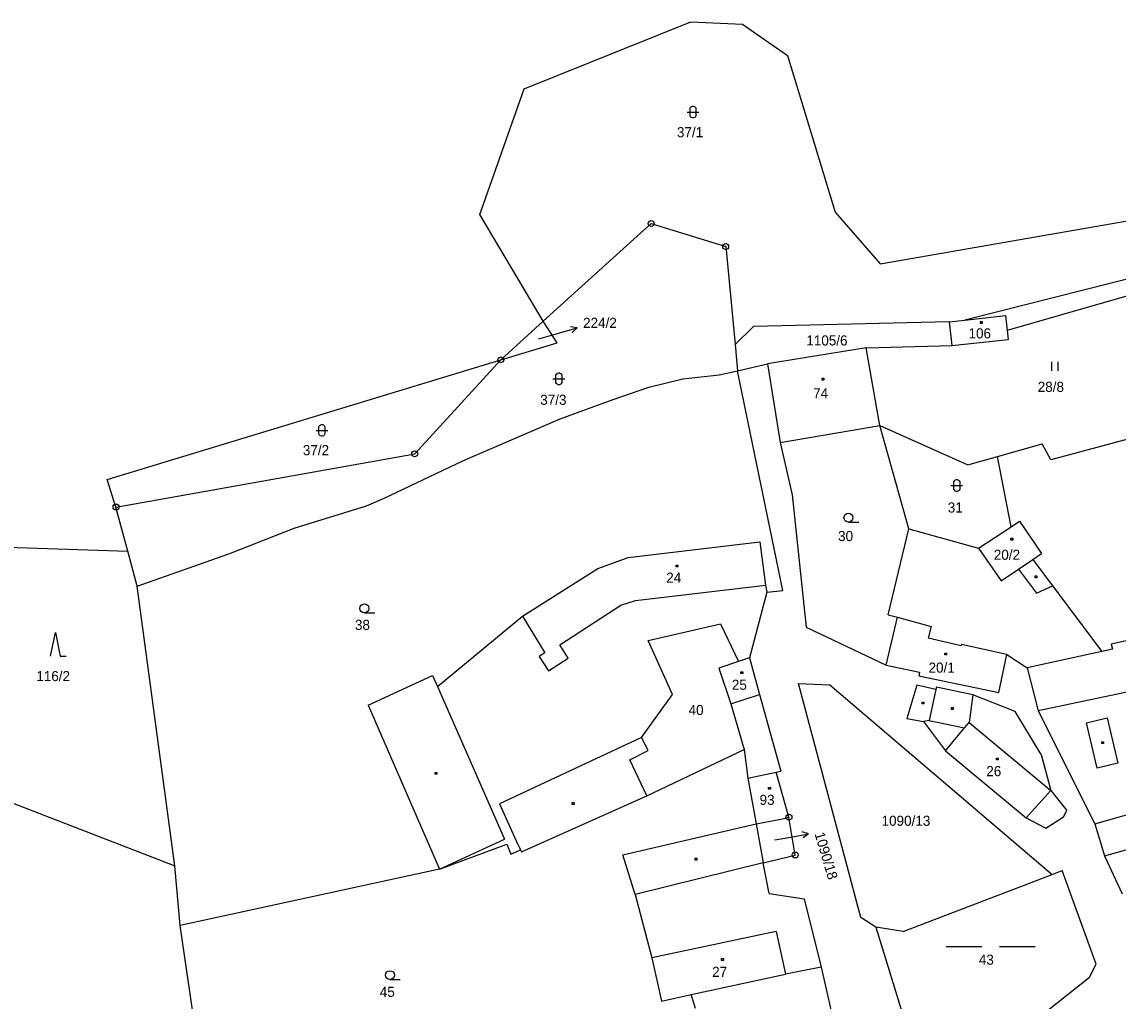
# Model space of a CAD drawing. Extents: x -794142 to -791199, y -1109267 to -1105626.
# Drawn here: x -793649.2 to -793464.4, y -1107661.7 to -1107496.8 of the extents above; entities that cross this region are included whole.
import ezdxf

# ---------------------------------------------------------------- set-up
doc = ezdxf.new("R2010")
doc.units = 0
for name, color, linetype in [('Komunikace', 7, 'Continuous'), ('Vrstva 1', 7, 'Continuous'), ('Vrstva 14', 7, 'Continuous'), ('Vrstva 15', 7, 'Continuous'), ('Vrstva 16', 7, 'Continuous'), ('Vrstva 2', 7, 'Continuous'), ('Vrstva 23', 7, 'Continuous'), ('Vrstva 25', 7, 'Continuous'), ('Vrstva 28', 7, 'Continuous')]:
    doc.layers.add(name, color=color, linetype=linetype)

msp = doc.modelspace()

# ---------------------------------------------------------------- linework, layer by layer
at = {"layer": 'Komunikace'}
for p, q in [((-793562.08, -1107550.13), (-793558.49, -1107549.12)), ((-793522.25, -1107634.57), (-793519.56, -1107634.08))]:
    msp.add_line(p, q, dxfattribs=at)
at = {"layer": 'Vrstva 1'}
for p, q in [((-793564.51, -1107508.01), (-793536.44, -1107496.75)), ((-793536.44, -1107496.75), (-793527.72, -1107497.14)), ((-793527.72, -1107497.14), (-793520.17, -1107502.43)), ((-793520.17, -1107502.43), (-793512.09, -1107528.82)), ((-793571.97, -1107529.21), (-793564.51, -1107508.01)), ((-793561.34, -1107547.18), (-793571.97, -1107529.21)), ((-793512.09, -1107528.82), (-793504.55, -1107537.5)), ((-793504.55, -1107537.5), (-793451, -1107528.21)), ((-793561.34, -1107547.18), (-793543.11, -1107530.72)), ((-793543.11, -1107530.72), (-793530.56, -1107534.6)), ((-793530.56, -1107534.6), (-793528.97, -1107551.12)), ((-793490.03, -1107546.86), (-793446.99, -1107536)), ((-793446.9, -1107538.36), (-793483.13, -1107548.72)), ((-793490.28, -1107546.99), (-793483.4, -1107546.22)), ((-793483.4, -1107546.22), (-793483.13, -1107548.72)), ((-793568.46, -1107553.68), (-793561.34, -1107547.18)), ((-793558.98, -1107550.83), (-793561.34, -1107547.18)), ((-793525.88, -1107548.06), (-793528.97, -1107551.12)), ((-793492.91, -1107547.28), (-793525.88, -1107548.06)), ((-793492.91, -1107547.28), (-793490.28, -1107546.99)), ((-793492.91, -1107547.28), (-793492.47, -1107551.26)), ((-793490.28, -1107546.99), (-793490.03, -1107546.86)), ((-793492.47, -1107551.26), (-793482.96, -1107550.23)), ((-793483.13, -1107548.72), (-793482.96, -1107550.23)), ((-793568.46, -1107553.68), (-793558.98, -1107550.83)), ((-793528.97, -1107551.12), (-793528.55, -1107555.52)), ((-793506.86, -1107551.68), (-793523.53, -1107554.36)), ((-793506.86, -1107551.68), (-793492.47, -1107551.26)), ((-793504.59, -1107564.72), (-793506.86, -1107551.68)), ((-793634.8, -1107573.86), (-793568.46, -1107553.68)), ((-793582.97, -1107569.53), (-793568.46, -1107553.68)), ((-793531.65, -1107556.22), (-793528.55, -1107555.52)), ((-793528.55, -1107555.52), (-793523.53, -1107554.36)), ((-793520.95, -1107592.54), (-793528.55, -1107555.52)), ((-793523.53, -1107554.36), (-793521.35, -1107567.62)), ((-793543.5, -1107558.28), (-793537.76, -1107556.9)), ((-793537.76, -1107556.9), (-793531.65, -1107556.22)), ((-793549.67, -1107560.44), (-793543.5, -1107558.28)), ((-793558.46, -1107563.63), (-793549.67, -1107560.44)), ((-793440.7, -1107561.08), (-793475.75, -1107570.55)), ((-793574.87, -1107570.69), (-793558.46, -1107563.63)), ((-793521.35, -1107567.62), (-793504.59, -1107564.72)), ((-793499.71, -1107582.15), (-793504.59, -1107564.72)), ((-793504.59, -1107564.72), (-793489.74, -1107571.38)), ((-793521.35, -1107567.62), (-793519.37, -1107576.41)), ((-793484.77, -1107569.98), (-793477.23, -1107567.86)), ((-793475.75, -1107570.55), (-793477.23, -1107567.86)), ((-793633.32, -1107578.48), (-793582.97, -1107569.53)), ((-793489.74, -1107571.38), (-793484.77, -1107569.98)), ((-793482.47, -1107581.81), (-793484.77, -1107569.98)), ((-793588.25, -1107577.02), (-793574.87, -1107570.69)), ((-793633.32, -1107578.48), (-793634.8, -1107573.86)), ((-793591.11, -1107578.26), (-793588.25, -1107577.02)), ((-793519.37, -1107576.41), (-793517.02, -1107598.72)), ((-793631.34, -1107585.92), (-793633.32, -1107578.48)), ((-793603.3, -1107582.04), (-793591.11, -1107578.26)), ((-793482.47, -1107581.81), (-793481.04, -1107580.87)), ((-793481.04, -1107580.87), (-793477.33, -1107586.32)), ((-793614.32, -1107586.39), (-793603.3, -1107582.04)), ((-793503.15, -1107596.63), (-793499.71, -1107582.15)), ((-793499.71, -1107582.15), (-793487.95, -1107585.41)), ((-793487.95, -1107585.41), (-793482.47, -1107581.81)), ((-793661.24, -1107584.9), (-793631.34, -1107585.92)), ((-793546.97, -1107587), (-793524.79, -1107584.34)), ((-793524.79, -1107584.34), (-793523.85, -1107591.64)), ((-793487.95, -1107585.41), (-793484.11, -1107590.94)), ((-793629.77, -1107591.83), (-793631.34, -1107585.92)), ((-793629.77, -1107591.83), (-793614.32, -1107586.39)), ((-793552.13, -1107588.82), (-793546.97, -1107587)), ((-793478.78, -1107587.3), (-793477.33, -1107586.32)), ((-793478.78, -1107587.3), (-793475.48, -1107591.74)), ((-793564.81, -1107596.85), (-793552.13, -1107588.82)), ((-793484.11, -1107590.94), (-793481.19, -1107588.95)), ((-793481.19, -1107588.95), (-793478.19, -1107592.97)), ((-793623.43, -1107638.94), (-793629.77, -1107591.83)), ((-793523.61, -1107592.83), (-793526.57, -1107603.91)), ((-793523.85, -1107591.64), (-793523.61, -1107592.83)), ((-793523.61, -1107592.83), (-793520.95, -1107592.54)), ((-793478.19, -1107592.97), (-793475.48, -1107591.74)), ((-793475.48, -1107591.74), (-793467.16, -1107602.8)), ((-793431.25, -1107594.06), (-793465.58, -1107601.57)), ((-793579.16, -1107608.74), (-793564.81, -1107596.85)), ((-793543.65, -1107600.98), (-793531.43, -1107598.14)), ((-793531.43, -1107598.14), (-793528.41, -1107604.53)), ((-793503.52, -1107605.14), (-793501.58, -1107597.06)), ((-793503.15, -1107596.63), (-793501.58, -1107597.06)), ((-793517.02, -1107598.72), (-793503.52, -1107605.14)), ((-793539.51, -1107610.04), (-793543.65, -1107600.98)), ((-793465.58, -1107601.57), (-793465.37, -1107602.41)), ((-793526.57, -1107603.91), (-793528.41, -1107604.53)), ((-793526.57, -1107603.91), (-793524.85, -1107610.06)), ((-793484.51, -1107609.71), (-793483.2, -1107603.32)), ((-793483.2, -1107603.32), (-793479.75, -1107605.56)), ((-793467.16, -1107602.8), (-793479.75, -1107605.56)), ((-793465.37, -1107602.41), (-793467.16, -1107602.8)), ((-793528.41, -1107604.53), (-793531.74, -1107605.64)), ((-793531.74, -1107605.64), (-793529.67, -1107611.65)), ((-793503.52, -1107605.14), (-793497.9, -1107606.31)), ((-793479.75, -1107605.56), (-793477.9, -1107612.84)), ((-793590.84, -1107611.87), (-793579.98, -1107606.86)), ((-793579.98, -1107606.86), (-793579.16, -1107608.74)), ((-793497.9, -1107606.31), (-793498.02, -1107606.9)), ((-793498.02, -1107606.9), (-793484.51, -1107609.71)), ((-793507.76, -1107647.63), (-793518.29, -1107608.24)), ((-793518.29, -1107608.24), (-793512.98, -1107608.42)), ((-793512.98, -1107608.42), (-793475.56, -1107640.37)), ((-793498.35, -1107608.48), (-793500.03, -1107614.1)), ((-793495.12, -1107609.25), (-793498.35, -1107608.48)), ((-793495.03, -1107608.86), (-793495.12, -1107609.25)), ((-793488.91, -1107610.13), (-793495.03, -1107608.86)), ((-793544.73, -1107617.33), (-793539.51, -1107610.04)), ((-793524.85, -1107610.06), (-793521.24, -1107622.96)), ((-793481.78, -1107612.95), (-793488.91, -1107610.13)), ((-793590.84, -1107611.87), (-793578.81, -1107639.51)), ((-793529.67, -1107611.65), (-793527.47, -1107619.34)), ((-793477.36, -1107620.16), (-793481.78, -1107612.95)), ((-793477.9, -1107612.84), (-793468.37, -1107631.84)), ((-793500.03, -1107614.1), (-793497.24, -1107614.63)), ((-793497.24, -1107614.63), (-793493.53, -1107619.55)), ((-793543.64, -1107619.51), (-793544.73, -1107617.33)), ((-793546.72, -1107621.05), (-793543.64, -1107619.51)), ((-793543.85, -1107627.13), (-793527.47, -1107619.34)), ((-793527.47, -1107619.34), (-793526.82, -1107624.17)), ((-793493.53, -1107619.55), (-793479.92, -1107630.86)), ((-793477.36, -1107620.16), (-793475.77, -1107626.23)), ((-793543.85, -1107627.13), (-793546.72, -1107621.05)), ((-793526.82, -1107624.17), (-793522.07, -1107623.14)), ((-793526.82, -1107624.17), (-793525.43, -1107631.85)), ((-793522.07, -1107623.14), (-793521.24, -1107622.96)), ((-793519.9, -1107630.74), (-793522.07, -1107623.14)), ((-793468.37, -1107631.84), (-793442.45, -1107624.47)), ((-793656.17, -1107626.24), (-793623.43, -1107638.94)), ((-793565, -1107636.6), (-793543.85, -1107627.13)), ((-793475.77, -1107626.23), (-793473.06, -1107629.61)), ((-793473.64, -1107630.69), (-793473.06, -1107629.61)), ((-793525.43, -1107631.85), (-793520.71, -1107630.98)), ((-793520.71, -1107630.98), (-793519.9, -1107630.74)), ((-793518.84, -1107637.11), (-793519.9, -1107630.74)), ((-793479.92, -1107630.86), (-793476.58, -1107632.61)), ((-793476.58, -1107632.61), (-793473.64, -1107630.69)), ((-793547.91, -1107637.07), (-793525.43, -1107631.85)), ((-793525.43, -1107631.85), (-793524.22, -1107638.45)), ((-793468.37, -1107631.84), (-793466.69, -1107637.27)), ((-793578.81, -1107639.51), (-793567.47, -1107635.31)), ((-793567.47, -1107635.31), (-793566.75, -1107636.95)), ((-793566.75, -1107636.95), (-793565.17, -1107636.24)), ((-793565.17, -1107636.24), (-793565, -1107636.6)), ((-793545.82, -1107643.75), (-793547.91, -1107637.07)), ((-793524.22, -1107638.45), (-793518.84, -1107637.11)), ((-793622.53, -1107649), (-793623.43, -1107638.94)), ((-793523.25, -1107643.62), (-793524.22, -1107638.45)), ((-793466.69, -1107637.27), (-793463.74, -1107643.66)), ((-793578.81, -1107639.51), (-793622.53, -1107649)), ((-793500.63, -1107650), (-793475.56, -1107640.37)), ((-793475.56, -1107640.37), (-793473.87, -1107639.72)), ((-793468.09, -1107655.5), (-793473.87, -1107639.72)), ((-793545.82, -1107643.75), (-793543.02, -1107654.43)), ((-793523.25, -1107643.62), (-793517.36, -1107644.49)), ((-793517.36, -1107644.49), (-793514.47, -1107656.01)), ((-793505.24, -1107649.29), (-793507.76, -1107647.63)), ((-793616.94, -1107686.45), (-793622.53, -1107649)), ((-793500.63, -1107650), (-793505.24, -1107649.29)), ((-793505.24, -1107649.29), (-793498.42, -1107671.41)), ((-793543.02, -1107654.43), (-793541.39, -1107661.71)), ((-793469.23, -1107657.69), (-793468.09, -1107655.5)), ((-793536.37, -1107660.62), (-793520.47, -1107657.18)), ((-793514.47, -1107656.01), (-793520.47, -1107657.18)), ((-793514.47, -1107656.01), (-793510.68, -1107672.43)), ((-793476.62, -1107663.51), (-793469.23, -1107657.69)), ((-793541.39, -1107661.71), (-793536.37, -1107660.62)), ((-793535.65, -1107662.97), (-793536.37, -1107660.62))]:
    msp.add_line(p, q, dxfattribs=at)
at = {"layer": 'Vrstva 16'}
for p, q in [((-793558.49, -1107549.12), (-793555.602, -1107548.304)), ((-793555.602, -1107548.304), (-793556.701, -1107548.095)), ((-793555.602, -1107548.304), (-793556.429, -1107549.057)), ((-793516.608, -1107633.541), (-793517.682, -1107633.228)), ((-793519.56, -1107634.08), (-793516.608, -1107633.541)), ((-793516.608, -1107633.541), (-793517.502, -1107634.212))]:
    msp.add_line(p, q, dxfattribs=at)
at = {"layer": 'Vrstva 2'}
for p, q in [((-793481.19, -1107588.95), (-793478.78, -1107587.3)), ((-793545.77, -1107594.21), (-793523.85, -1107591.64)), ((-793548.23, -1107595), (-793545.77, -1107594.21)), ((-793558.52, -1107601.69), (-793548.23, -1107595)), ((-793564.81, -1107596.85), (-793561.02, -1107603.07)), ((-793501.58, -1107597.06), (-793495.9, -1107598.62)), ((-793495.9, -1107598.62), (-793496.44, -1107600.59)), ((-793557.1, -1107603.97), (-793558.52, -1107601.69)), ((-793490.85, -1107601.89), (-793496.44, -1107600.59)), ((-793490.82, -1107601.62), (-793490.85, -1107601.89)), ((-793483.2, -1107603.32), (-793490.82, -1107601.62)), ((-793561.02, -1107603.07), (-793561.97, -1107603.64)), ((-793561.97, -1107603.64), (-793560.44, -1107606.09)), ((-793560.44, -1107606.09), (-793557.1, -1107603.97)), ((-793443.32, -1107605.55), (-793477.9, -1107612.84)), ((-793579.16, -1107608.74), (-793567.85, -1107634.45)), ((-793495.12, -1107609.25), (-793496.27, -1107614.43)), ((-793529.67, -1107611.65), (-793524.85, -1107610.06)), ((-793488.91, -1107610.13), (-793489.55, -1107614.76)), ((-793496.27, -1107614.43), (-793497.24, -1107614.63)), ((-793496.27, -1107614.43), (-793490.32, -1107615.69)), ((-793490.32, -1107615.69), (-793489.55, -1107614.76)), ((-793489.55, -1107614.76), (-793475.77, -1107626.23)), ((-793469.75, -1107614.84), (-793466.27, -1107613.99)), ((-793467.97, -1107622.46), (-793469.75, -1107614.84)), ((-793466.27, -1107613.99), (-793464.49, -1107621.61)), ((-793493.53, -1107619.55), (-793490.32, -1107615.69)), ((-793544.73, -1107617.33), (-793568.68, -1107628.5)), ((-793464.49, -1107621.61), (-793467.97, -1107622.46)), ((-793479.92, -1107630.86), (-793475.77, -1107626.23)), ((-793568.68, -1107628.5), (-793565.9, -1107634.73)), ((-793466.69, -1107637.27), (-793440.87, -1107629.99)), ((-793578.81, -1107639.51), (-793567.85, -1107634.45)), ((-793565.9, -1107634.73), (-793565.17, -1107636.24)), ((-793524.22, -1107638.45), (-793545.82, -1107643.75)), ((-793522.05, -1107649.99), (-793543.02, -1107654.43)), ((-793522.05, -1107649.99), (-793520.47, -1107657.18))]:
    msp.add_line(p, q, dxfattribs=at)
at = {"layer": 'Vrstva 23'}
for p, q in [((-793536.57, -1107511.33), (-793536.47, -1107511.13)), ((-793536.57, -1107512.53), (-793536.57, -1107511.33)), ((-793536.47, -1107511.13), (-793536.37, -1107511.03)), ((-793536.37, -1107511.03), (-793536.17, -1107510.93)), ((-793536.17, -1107510.93), (-793535.97, -1107510.93)), ((-793535.97, -1107510.93), (-793535.77, -1107511.03)), ((-793535.77, -1107511.03), (-793535.67, -1107511.13)), ((-793535.67, -1107511.13), (-793535.57, -1107511.33)), ((-793535.57, -1107511.33), (-793535.57, -1107512.53)), ((-793537.07, -1107511.93), (-793535.07, -1107511.93)), ((-793536.47, -1107512.73), (-793536.57, -1107512.53)), ((-793536.37, -1107512.83), (-793536.47, -1107512.73)), ((-793536.17, -1107512.93), (-793536.37, -1107512.83)), ((-793535.97, -1107512.93), (-793536.17, -1107512.93)), ((-793535.77, -1107512.83), (-793535.97, -1107512.93)), ((-793535.67, -1107512.73), (-793535.77, -1107512.83)), ((-793535.57, -1107512.53), (-793535.67, -1107512.73)), ((-793475.57, -1107555.53), (-793475.57, -1107554.03)), ((-793474.57, -1107554.03), (-793474.57, -1107555.53)), ((-793558.97, -1107555.99), (-793558.77, -1107555.89)), ((-793558.77, -1107555.89), (-793558.57, -1107555.89)), ((-793558.57, -1107555.89), (-793558.37, -1107555.99)), ((-793559.67, -1107556.89), (-793557.67, -1107556.89)), ((-793559.17, -1107556.29), (-793559.07, -1107556.09)), ((-793559.17, -1107557.49), (-793559.17, -1107556.29)), ((-793559.07, -1107557.69), (-793559.17, -1107557.49)), ((-793559.07, -1107556.09), (-793558.97, -1107555.99)), ((-793558.97, -1107557.79), (-793559.07, -1107557.69)), ((-793558.37, -1107555.99), (-793558.27, -1107556.09)), ((-793558.27, -1107557.69), (-793558.37, -1107557.79)), ((-793558.27, -1107556.09), (-793558.17, -1107556.29)), ((-793558.17, -1107557.49), (-793558.27, -1107557.69)), ((-793558.17, -1107556.29), (-793558.17, -1107557.49)), ((-793558.77, -1107557.89), (-793558.97, -1107557.79)), ((-793558.57, -1107557.89), (-793558.77, -1107557.89)), ((-793558.37, -1107557.79), (-793558.57, -1107557.89)), ((-793599.11, -1107564.97), (-793599.01, -1107564.77)), ((-793599.11, -1107566.17), (-793599.11, -1107564.97)), ((-793599.01, -1107564.77), (-793598.91, -1107564.67)), ((-793598.91, -1107564.67), (-793598.71, -1107564.57)), ((-793598.71, -1107564.57), (-793598.51, -1107564.57)), ((-793598.51, -1107564.57), (-793598.31, -1107564.67)), ((-793598.31, -1107564.67), (-793598.21, -1107564.77)), ((-793598.21, -1107564.77), (-793598.11, -1107564.97)), ((-793598.11, -1107564.97), (-793598.11, -1107566.17)), ((-793599.61, -1107565.57), (-793597.61, -1107565.57)), ((-793599.01, -1107566.37), (-793599.11, -1107566.17)), ((-793598.91, -1107566.47), (-793599.01, -1107566.37)), ((-793598.71, -1107566.57), (-793598.91, -1107566.47)), ((-793598.51, -1107566.57), (-793598.71, -1107566.57)), ((-793598.31, -1107566.47), (-793598.51, -1107566.57)), ((-793598.21, -1107566.37), (-793598.31, -1107566.47)), ((-793598.11, -1107566.17), (-793598.21, -1107566.37)), ((-793492.12, -1107574.25), (-793492.02, -1107574.05)), ((-793492.12, -1107575.45), (-793492.12, -1107574.25)), ((-793492.02, -1107574.05), (-793491.92, -1107573.95)), ((-793491.92, -1107573.95), (-793491.72, -1107573.85)), ((-793491.72, -1107573.85), (-793491.52, -1107573.85)), ((-793491.52, -1107573.85), (-793491.32, -1107573.95)), ((-793491.32, -1107573.95), (-793491.22, -1107574.05)), ((-793491.22, -1107574.05), (-793491.12, -1107574.25)), ((-793491.12, -1107574.25), (-793491.12, -1107575.45)), ((-793492.62, -1107574.85), (-793490.62, -1107574.85)), ((-793492.02, -1107575.65), (-793492.12, -1107575.45)), ((-793491.92, -1107575.75), (-793492.02, -1107575.65)), ((-793491.72, -1107575.85), (-793491.92, -1107575.75)), ((-793491.52, -1107575.85), (-793491.72, -1107575.85)), ((-793491.32, -1107575.75), (-793491.52, -1107575.85)), ((-793491.22, -1107575.65), (-793491.32, -1107575.75)), ((-793491.12, -1107575.45), (-793491.22, -1107575.65)), ((-793509.87, -1107581.02), (-793508.12, -1107581.02)), ((-793591.45, -1107596.3), (-793589.7, -1107596.3)), ((-793644.34, -1107603.62), (-793643.54, -1107599.62)), ((-793643.54, -1107599.62), (-793642.74, -1107603.62)), ((-793642.74, -1107603.62), (-793641.74, -1107603.62)), ((-793493.39, -1107652.53), (-793487.39, -1107652.53)), ((-793484.39, -1107652.53), (-793478.39, -1107652.53)), ((-793587.15, -1107658.1), (-793585.4, -1107658.1))]:
    msp.add_line(p, q, dxfattribs=at)
for centre in [(-793509.87, -1107580.27), (-793591.45, -1107595.55), (-793587.15, -1107657.35)]:
    msp.add_circle(centre, 0.75, dxfattribs=at)
at = {"layer": 'Vrstva 25'}
for p, q in [((-793487.61, -1107547.25), (-793487.31, -1107547.25)), ((-793487.61, -1107547.55), (-793487.61, -1107547.25)), ((-793487.31, -1107547.55), (-793487.61, -1107547.55)), ((-793487.31, -1107547.25), (-793487.31, -1107547.55)), ((-793514.3, -1107556.78), (-793514, -1107556.78)), ((-793514.3, -1107557.08), (-793514.3, -1107556.78)), ((-793514, -1107557.08), (-793514.3, -1107557.08)), ((-793514, -1107556.78), (-793514, -1107557.08)), ((-793482.49, -1107583.75), (-793482.19, -1107583.75)), ((-793482.49, -1107584.05), (-793482.49, -1107583.75)), ((-793482.19, -1107584.05), (-793482.49, -1107584.05)), ((-793482.19, -1107583.75), (-793482.19, -1107584.05)), ((-793538.93, -1107588.25), (-793538.63, -1107588.25)), ((-793538.93, -1107588.55), (-793538.93, -1107588.25)), ((-793538.63, -1107588.55), (-793538.93, -1107588.55)), ((-793538.63, -1107588.25), (-793538.63, -1107588.55)), ((-793478.41, -1107590.1), (-793478.11, -1107590.1)), ((-793478.41, -1107590.4), (-793478.41, -1107590.1)), ((-793478.11, -1107590.4), (-793478.41, -1107590.4)), ((-793478.11, -1107590.1), (-793478.11, -1107590.4)), ((-793493.64, -1107603.08), (-793493.34, -1107603.08)), ((-793493.64, -1107603.38), (-793493.64, -1107603.08)), ((-793493.34, -1107603.38), (-793493.64, -1107603.38)), ((-793493.34, -1107603.08), (-793493.34, -1107603.38)), ((-793527.98, -1107606.25), (-793527.68, -1107606.25)), ((-793527.98, -1107606.55), (-793527.98, -1107606.25)), ((-793527.68, -1107606.55), (-793527.98, -1107606.55)), ((-793527.68, -1107606.25), (-793527.68, -1107606.55)), ((-793497.45, -1107611.36), (-793497.15, -1107611.36)), ((-793497.45, -1107611.66), (-793497.45, -1107611.36)), ((-793497.15, -1107611.66), (-793497.45, -1107611.66)), ((-793497.15, -1107611.36), (-793497.15, -1107611.66)), ((-793492.52, -1107612.28), (-793492.22, -1107612.28)), ((-793492.52, -1107612.58), (-793492.52, -1107612.28)), ((-793492.22, -1107612.58), (-793492.52, -1107612.58)), ((-793492.22, -1107612.28), (-793492.22, -1107612.58)), ((-793467.19, -1107618.04), (-793466.89, -1107618.04)), ((-793467.19, -1107618.34), (-793467.19, -1107618.04)), ((-793466.89, -1107618.34), (-793467.19, -1107618.34)), ((-793466.89, -1107618.04), (-793466.89, -1107618.34)), ((-793484.94, -1107620.78), (-793484.64, -1107620.78)), ((-793484.94, -1107621.08), (-793484.94, -1107620.78)), ((-793484.64, -1107621.08), (-793484.94, -1107621.08)), ((-793484.64, -1107620.78), (-793484.64, -1107621.08)), ((-793579.53, -1107623.19), (-793579.23, -1107623.19)), ((-793579.53, -1107623.49), (-793579.53, -1107623.19)), ((-793579.23, -1107623.49), (-793579.53, -1107623.49)), ((-793579.23, -1107623.19), (-793579.23, -1107623.49)), ((-793523.32, -1107625.71), (-793523.02, -1107625.71)), ((-793523.32, -1107626.01), (-793523.32, -1107625.71)), ((-793523.02, -1107626.01), (-793523.32, -1107626.01)), ((-793523.02, -1107625.71), (-793523.02, -1107626.01)), ((-793556.42, -1107628.28), (-793556.12, -1107628.28)), ((-793556.42, -1107628.58), (-793556.42, -1107628.28)), ((-793556.12, -1107628.58), (-793556.42, -1107628.58)), ((-793556.12, -1107628.28), (-793556.12, -1107628.58)), ((-793535.73, -1107637.66), (-793535.43, -1107637.66)), ((-793535.73, -1107637.96), (-793535.73, -1107637.66)), ((-793535.43, -1107637.96), (-793535.73, -1107637.96)), ((-793535.43, -1107637.66), (-793535.43, -1107637.96)), ((-793531.25, -1107654.56), (-793530.95, -1107654.56)), ((-793531.25, -1107654.86), (-793531.25, -1107654.56)), ((-793530.95, -1107654.86), (-793531.25, -1107654.86)), ((-793530.95, -1107654.56), (-793530.95, -1107654.86))]:
    msp.add_line(p, q, dxfattribs=at)
at = {"layer": 'Vrstva 28'}
for centre, radius in [((-793543.11, -1107530.72), 0.5), ((-793543.11, -1107530.72), 0.01), ((-793530.56, -1107534.6), 0.5), ((-793530.56, -1107534.6), 0.01), ((-793568.46, -1107553.68), 0.5), ((-793568.46, -1107553.68), 0.01), ((-793582.97, -1107569.53), 0.5), ((-793582.97, -1107569.53), 0.01), ((-793633.32, -1107578.48), 0.5), ((-793633.32, -1107578.48), 0.01), ((-793519.9, -1107630.74), 0.5), ((-793519.9, -1107630.74), 0.01), ((-793518.84, -1107637.11), 0.5), ((-793518.84, -1107637.11), 0.01)]:
    msp.add_circle(centre, radius, dxfattribs=at)

# ---------------------------------------------------------------- texts
at = {"layer": 'Vrstva 14'}
for s, height, p in [('37/1', 1.7, (-793538.78, -1107516.18)), ('224/2', 0.1, (-793562.282, -1107550.13)), ('1105/6', 1.7, (-793516.972, -1107551.26)), ('28/8', 1.7, (-793477.969, -1107559.08)), ('37/3', 1.7, (-793561.817, -1107561.26)), ('37/2', 1.7, (-793601.826, -1107569.75)), ('31', 1.7, (-793493.13, -1107579.41)), ('30', 1.7, (-793511.616, -1107584.22)), ('38', 1.7, (-793593.047, -1107599.18)), ('116/2', 1.7, (-793646.756, -1107607.82)), ('40', 1.7, (-793536.812, -1107613.53)), ('1090/13', 1.7, (-793504.285, -1107632.19)), ('1090/18', 0.1, (-793522.515, -1107634.57)), ('43', 1.7, (-793487.893, -1107655.6)), ('45', 1.7, (-793588.859, -1107661.01))]:
    msp.add_text(s, height=height, dxfattribs=at).set_placement(p)
at = {"layer": 'Vrstva 15'}
for s, p in [('106', (-793489.629, -1107550.07)), ('74', (-793515.819, -1107560.16)), ('20/2', (-793485.369, -1107587.37)), ('24', (-793540.582, -1107591.23)), ('20/1', (-793496.372, -1107606.39)), ('25', (-793529.523, -1107609.28)), ('26', (-793486.637, -1107623.83)), ('93', (-793524.847, -1107628.66)), ('27', (-793532.843, -1107657.65))]:
    msp.add_text(s, height=1.7, dxfattribs=at).set_placement(p)
at = {"layer": 'Vrstva 16'}
msp.add_text('224/2', height=1.7, dxfattribs=at).set_placement((-793554.6, -1107548.3))
msp.add_text('1090/18', height=1.7, rotation=286.52949, dxfattribs=at).set_placement((-793515.6, -1107633.53))

doc.saveas('drawing.dxf')
